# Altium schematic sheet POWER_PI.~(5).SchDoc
size A; SheetNumber: 1; SheetTotal: 2
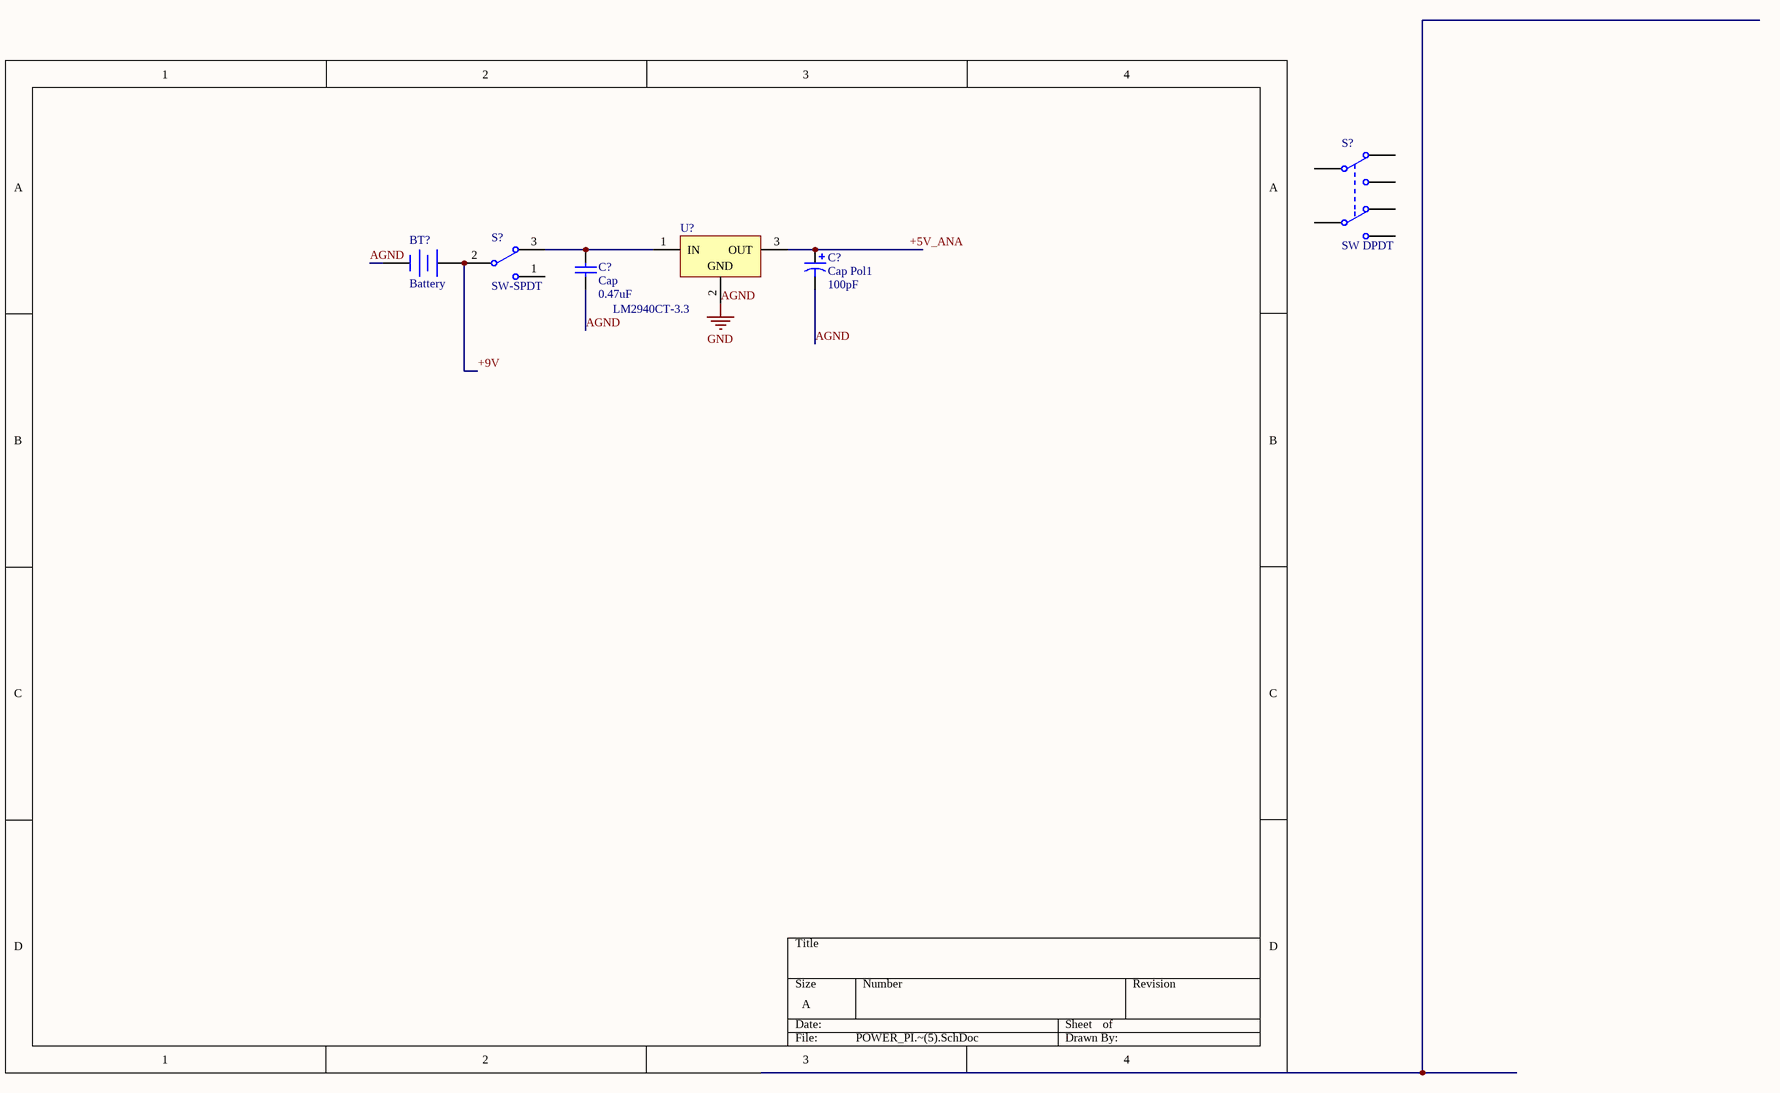
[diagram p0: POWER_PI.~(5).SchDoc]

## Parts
(Parts that share a designator on the sheet are numbered #1, #2 ... from top to bottom, then left to right.)
BT?  Battery  [BAT-2]
C?#1  Cap Pol1  value 100pF  [RB7.6-15]
C?#2  Cap  value 0.47uF  [RAD-0.3]
S?#1  SW DPDT  [SOT23-6_N]
S?#2  SW-SPDT  [SW DPST jameco]
U?  LM2940CT-3.3  [T03B]

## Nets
AGND: BT?.2(-) C?#1.2 C?#2.1 U?.2(GND)  [also labelled GND]
+5V_ANA: C?#1.1 U?.3(OUT)
+9V: BT?.1(+) S?#2.2
NetC?#2_2: C?#2.2 S?#2.3 U?.1(IN)

Not connected (* = marked no-connect by the designer): S?#1 1(COMMON1) 2(NC1) 3(NO1) 4(NC2) 5(COMMON2) 6(NO2); S?#2 1

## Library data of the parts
BT? = Battery: Multicell Battery
C?#1 = Cap Pol1: Polarized Capacitor (Radial)
C?#2 = Cap: Capacitor
S?#1 = SW DPDT: Switch
S?#2 = SW-SPDT: SPDT Subminiature Toggle Switch, Right Angle Mounting, Vertical Actuation
U? = LM2940CT-5.0: 1A Low Dropout Regulator, 3-pin TO-220; Manufacturer: National Semiconductor; PackageTopMarking: NSUZXYTTE#*LM2940CT*-5.0 P+; PowerWise: N; CompType: LDO IC; High-Reliability: Y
